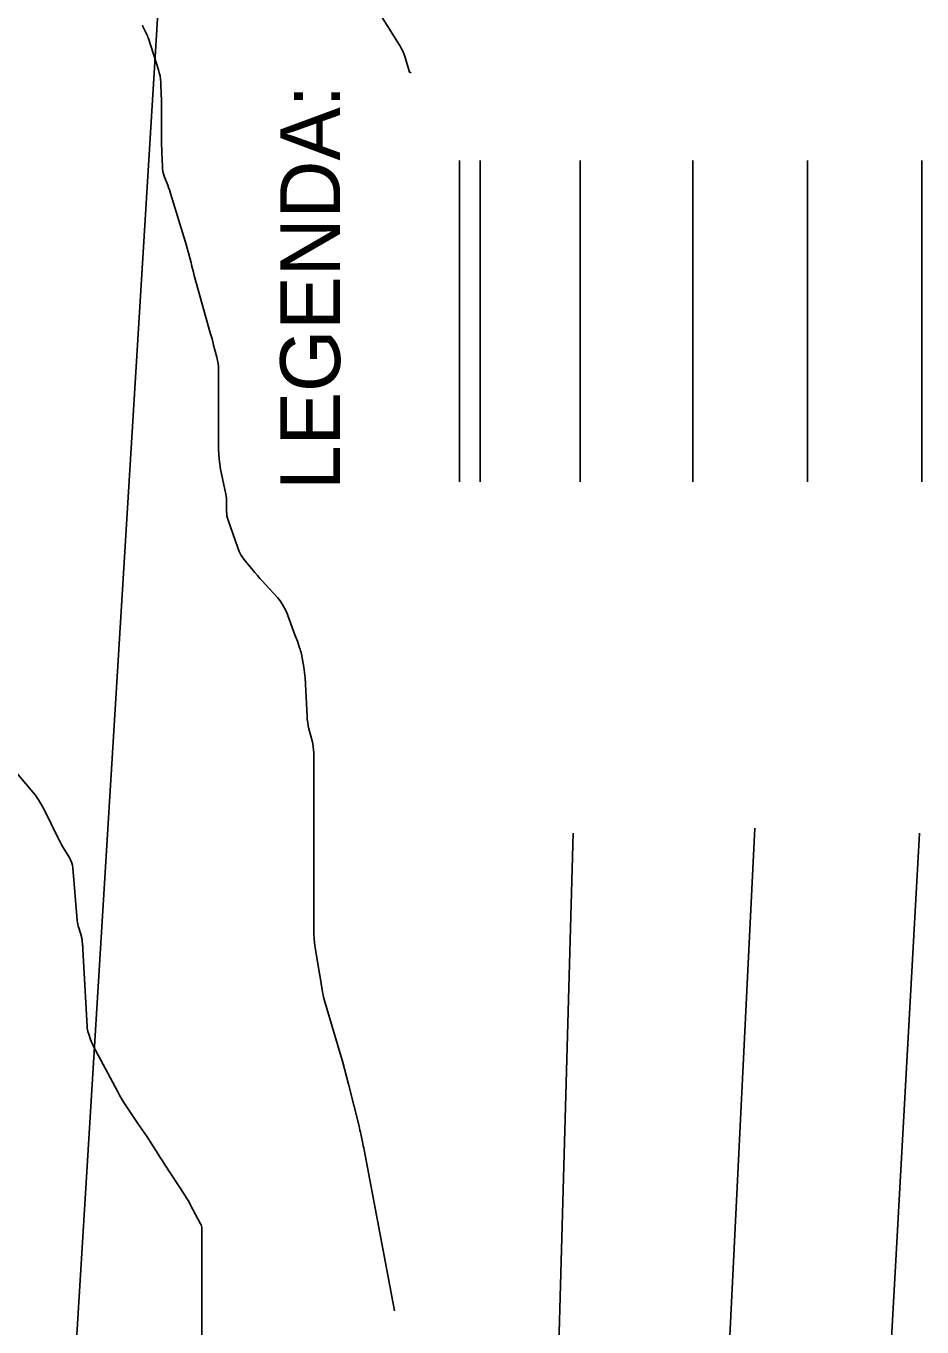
# Model space of a CAD drawing. Extents: x -534410 to -534262, y -1190162 to -1189584.
# Drawn here: x -534343.12 to -534324.41, y -1189644.95 to -1189617.8 of the extents above; entities that cross this region are included whole.
import ezdxf

# ---------------------------------------------------------------- set-up
doc = ezdxf.new("R2010")
doc.units = 0
for name, color, linetype in [('07_ELEKTRO', 7, 'Continuous'), ('30', 7, 'Continuous'), ('31', 7, 'Continuous'), ('_N_osa', 7, 'Continuous'), ('_N_tučná', 7, 'Continuous'), ('Hranice parcel', 7, 'Continuous'), ('LEGENDA', 7, 'Continuous')]:
    doc.layers.add(name, color=color, linetype=linetype)

msp = doc.modelspace()

# ---------------------------------------------------------------- linework, layer by layer
at = {"layer": '07_ELEKTRO'}
msp.add_line((-534324.407, -1189620.613), (-534324.407, -1189627.319), dxfattribs=at)
at = {"layer": '30'}
for points in [[(-534335.965, -1189617.168), (-534335.305, -1189618.224), (-534335.272, -1189618.281), (-534335.243, -1189618.34), (-534335.218, -1189618.4), (-534335.197, -1189618.463), (-534335.122, -1189618.717), (-534335.105, -1189618.765), (-534335.092, -1189618.78), (-534335.083, -1189618.762)], [(-534339.444, -1189646.526), (-534339.444, -1189642.9), (-534339.445, -1189642.873), (-534339.45, -1189642.846), (-534339.458, -1189642.821), (-534339.47, -1189642.796), (-534339.575, -1189642.601), (-534339.694, -1189642.379), (-534339.719, -1189642.335), (-534339.745, -1189642.29), (-534339.772, -1189642.247), (-534339.799, -1189642.203), (-534340.221, -1189641.557), (-534340.267, -1189641.486), (-534340.313, -1189641.414), (-534340.359, -1189641.343), (-534340.405, -1189641.272), (-534340.589, -1189640.987), (-534340.635, -1189640.916), (-534340.682, -1189640.845), (-534340.729, -1189640.775), (-534340.777, -1189640.704), (-534341.004, -1189640.371), (-534341.057, -1189640.291), (-534341.107, -1189640.21), (-534341.155, -1189640.128), (-534341.201, -1189640.044), (-534341.71, -1189639.084), (-534341.726, -1189639.052), (-534341.741, -1189639.02), (-534341.754, -1189638.987), (-534341.766, -1189638.954), (-534341.812, -1189638.82), (-534341.822, -1189638.786), (-534341.83, -1189638.752), (-534341.836, -1189638.717), (-534341.839, -1189638.682), (-534341.927, -1189637.078), (-534341.929, -1189637.054), (-534341.93, -1189637.031), (-534341.932, -1189637.008), (-534341.934, -1189636.984), (-534341.942, -1189636.891), (-534341.945, -1189636.868), (-534341.949, -1189636.845), (-534341.954, -1189636.822), (-534341.96, -1189636.8), (-534342.015, -1189636.623), (-534342.026, -1189636.586), (-534342.034, -1189636.549), (-534342.04, -1189636.511), (-534342.045, -1189636.473), (-534342.14, -1189635.37), (-534342.148, -1189635.312), (-534342.163, -1189635.255), (-534342.184, -1189635.201), (-534342.212, -1189635.15), (-534342.337, -1189634.946), (-534342.367, -1189634.895), (-534342.396, -1189634.843), (-534342.425, -1189634.791), (-534342.452, -1189634.738), (-534342.732, -1189634.169), (-534342.79, -1189634.059), (-534342.855, -1189633.952), (-534342.927, -1189633.85), (-534343.005, -1189633.752), (-534343.681, -1189632.954)]]:
    msp.add_lwpolyline(points, dxfattribs=at)
at = {"layer": '31'}
msp.add_lwpolyline([(-534335.421, -1189644.614), (-534335.428, -1189644.576), (-534335.436, -1189644.537), (-534335.443, -1189644.499), (-534335.45, -1189644.46), (-534336.057, -1189641.256), (-534336.064, -1189641.215), (-534336.073, -1189641.174), (-534336.081, -1189641.132), (-534336.089, -1189641.091), (-534336.124, -1189640.927), (-534336.133, -1189640.886), (-534336.142, -1189640.845), (-534336.151, -1189640.804), (-534336.161, -1189640.763), (-534336.382, -1189639.884), (-534336.423, -1189639.724), (-534336.465, -1189639.564), (-534336.509, -1189639.405), (-534336.555, -1189639.247), (-534336.887, -1189638.119), (-534336.901, -1189638.069), (-534336.914, -1189638.018), (-534336.925, -1189637.966), (-534336.934, -1189637.915), (-534336.976, -1189637.655), (-534337.001, -1189637.499), (-534337.077, -1189637.034), (-534337.091, -1189636.939), (-534337.1, -1189636.844), (-534337.106, -1189636.748), (-534337.108, -1189636.652), (-534337.108, -1189632.974), (-534337.11, -1189632.91), (-534337.116, -1189632.846), (-534337.127, -1189632.782), (-534337.141, -1189632.719), (-534337.208, -1189632.468), (-534337.223, -1189632.405), (-534337.234, -1189632.341), (-534337.243, -1189632.277), (-534337.248, -1189632.213), (-534337.288, -1189631.407), (-534337.292, -1189631.351), (-534337.298, -1189631.294), (-534337.306, -1189631.237), (-534337.315, -1189631.181), (-534337.366, -1189630.915), (-534337.373, -1189630.88), (-534337.381, -1189630.845), (-534337.391, -1189630.811), (-534337.403, -1189630.777), (-534337.45, -1189630.643), (-534337.462, -1189630.609), (-534337.475, -1189630.576), (-534337.487, -1189630.542), (-534337.499, -1189630.509), (-534337.679, -1189630.032), (-534337.715, -1189629.95), (-534337.758, -1189629.873), (-534337.808, -1189629.799), (-534337.865, -1189629.731), (-534338.124, -1189629.45), (-534338.177, -1189629.391), (-534338.23, -1189629.332), (-534338.282, -1189629.272), (-534338.334, -1189629.211), (-534338.538, -1189628.967), (-534338.586, -1189628.904), (-534338.628, -1189628.837), (-534338.664, -1189628.768), (-534338.693, -1189628.694), (-534338.896, -1189628.114), (-534338.91, -1189628.071), (-534338.919, -1189628.027), (-534338.925, -1189627.982), (-534338.927, -1189627.936), (-534338.927, -1189627.753), (-534338.928, -1189627.707), (-534338.931, -1189627.662), (-534338.937, -1189627.616), (-534338.945, -1189627.571), (-534339.053, -1189627.049), (-534339.071, -1189626.946), (-534339.084, -1189626.843), (-534339.092, -1189626.74), (-534339.095, -1189626.636), (-534339.095, -1189624.977), (-534339.097, -1189624.911), (-534339.103, -1189624.846), (-534339.114, -1189624.781), (-534339.129, -1189624.717), (-534339.197, -1189624.461), (-534339.214, -1189624.397), (-534339.231, -1189624.333), (-534339.249, -1189624.269), (-534339.267, -1189624.205), (-534339.601, -1189623.011), (-534339.61, -1189622.978), (-534339.619, -1189622.944), (-534339.641, -1189622.864), (-534339.646, -1189622.844), (-534339.651, -1189622.825), (-534339.663, -1189622.776), (-534339.67, -1189622.747), (-534339.724, -1189622.536), (-534339.734, -1189622.498), (-534339.744, -1189622.459), (-534339.755, -1189622.421), (-534339.766, -1189622.383), (-534340.091, -1189621.318), (-534340.106, -1189621.27), (-534340.122, -1189621.222), (-534340.138, -1189621.175), (-534340.156, -1189621.127), (-534340.228, -1189620.939), (-534340.244, -1189620.891), (-534340.256, -1189620.843), (-534340.264, -1189620.794), (-534340.268, -1189620.744), (-534340.28, -1189620.438), (-534340.282, -1189620.37), (-534340.284, -1189620.302), (-534340.285, -1189620.235), (-534340.285, -1189620.167), (-534340.285, -1189619.522), (-534340.286, -1189619.454), (-534340.287, -1189619.387), (-534340.288, -1189619.319), (-534340.291, -1189619.251), (-534340.303, -1189618.98), (-534340.308, -1189618.913), (-534340.317, -1189618.846), (-534340.332, -1189618.78), (-534340.35, -1189618.716), (-534340.561, -1189618.065), (-534340.571, -1189618.037), (-534340.582, -1189618.008), (-534340.594, -1189617.98), (-534340.607, -1189617.953), (-534340.661, -1189617.844), (-534340.673, -1189617.816), (-534340.684, -1189617.788)], dxfattribs=at)
at = {"layer": '_N_osa'}
for p, q in [((-534334.067, -1189627.319), (-534334.067, -1189620.613)), ((-534333.634, -1189627.319), (-534333.634, -1189620.613))]:
    msp.add_line(p, q, dxfattribs=at)
at = {"layer": '_N_tučná'}
msp.add_line((-534331.546, -1189627.319), (-534331.546, -1189620.613), dxfattribs=at)
at = {"layer": 'Hranice parcel'}
msp.add_line((-534326.799, -1189627.319), (-534326.799, -1189620.613), dxfattribs=at)
for points in [[(-534347.07, -1189935.15), (-534347.12, -1189900.1), (-534346.3, -1189826.77), (-534344.77, -1189736.43), (-534342.85, -1189658.07), (-534338.334, -1189584.47)], [(-534334.89, -1189942.46), (-534332.03, -1189880.06), (-534330.32, -1189744.92), (-534328.5, -1189646.74), (-534327.899, -1189634.546)], [(-534338.84, -1189942.48), (-534336.49, -1189881.83), (-534334.78, -1189743.85), (-534331.691, -1189634.648)], [(-534330.63, -1189942.43), (-534326.4, -1189862.47), (-534326.07, -1189744.82), (-534325.13, -1189646.79), (-534324.459, -1189634.648)]]:
    msp.add_lwpolyline(points, dxfattribs=at)
at = {"layer": 'LEGENDA'}
msp.add_line((-534329.192, -1189627.319), (-534329.192, -1189620.613), dxfattribs=at)

# ---------------------------------------------------------------- texts
msp.add_text('LEGENDA:', height=1.25, rotation=90, dxfattribs=at).set_placement((-534336.557, -1189627.487))

doc.saveas('drawing.dxf')
